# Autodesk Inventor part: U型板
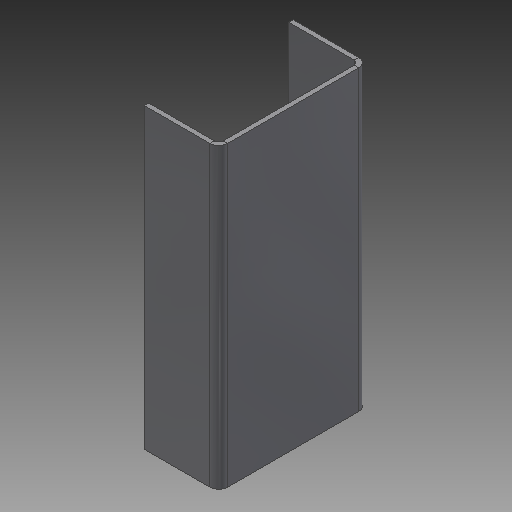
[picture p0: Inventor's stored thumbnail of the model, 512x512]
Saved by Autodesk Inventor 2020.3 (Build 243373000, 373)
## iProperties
RuleStatus: InUse
BeforeDocSave0: 重量提取
Part Number: U型板
Material: Q235B
Description: Metal
Document SubType Name: 钣金
Density: 7.85 g/cm^3
Sheet Metal Rule: 默认_mm
Appearance: Q235B
Mass: 895.546 g
Surface Area: 783.957 cm^2
Volume: 114.082 cm^3
名称: U型板
重量: 0.9
文件类型: 钣金件
规格材料: t3/Q235B
Author: 陈驹祥
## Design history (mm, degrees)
node "异形板1"
  sketch "草图3"
    geometry: L1 (0, 50)-(0, -50); L2 (0, -50)-(50, -50); L3 (0, 50)-(50, 50); 2 further points
    constraints: 6 end point, 1 coincident, 1 horizontal, 1 midpoint, 1 perpendicular, 1 vertical
    dimensions: "LD" = 100 distance of L1.start L1.end; "LB" = 50 distance of L1.end L2.end; "LA" = 50 distance of L1.start L3.end
node "实体3"
feature "平板1" dims "d7" = 3 (= 厚度), "d8" = 3 (= 折弯释压宽度), "d9" = 1.5 (= 折弯释压深度), "d10" = 6 (= 最小余量), "d11" = 3 (= 过渡半径), "d13" = 3 (= 折弯半径), "d14" = 3, "d15" = 12 (= 拐角释压尺寸), "d16" = 3 (= 间隙大小), "d17" = 3 (= Jacobi半径尺寸), "LC" = 200, "焊缝间隙" = 0.01
feature "折弯1" dims "d7" = 3 (= 厚度), "d8" = 3 (= 折弯释压宽度), "d9" = 1.5 (= 折弯释压深度), "d10" = 6 (= 最小余量), "d11" = 3 (= 过渡半径), "d13" = 3 (= 折弯半径), "d14" = 3, "焊缝间隙" = 0.01
feature "拐角1" dims "d14" = 3, "d15" = 12 (= 拐角释压尺寸), "d16" = 3 (= 间隙大小), "d17" = 3 (= Jacobi半径尺寸)
other parameters: "厚度" = 3, "K系数" = 4.4, "折弯半径" = 3 (= 厚度), "折弯释压宽度" = 3 (= 厚度), "折弯释压深度" = 1.5 (= 0.5 x 厚度), "拐角释压尺寸" = 12 (= 4 x 厚度), "最小余量" = 6 (= 2 x 厚度), "过渡半径" = 3 (= 折弯半径), "Jacobi半径尺寸" = 3 (= 折弯半径), "间隙大小" = 3 (= 厚度)
